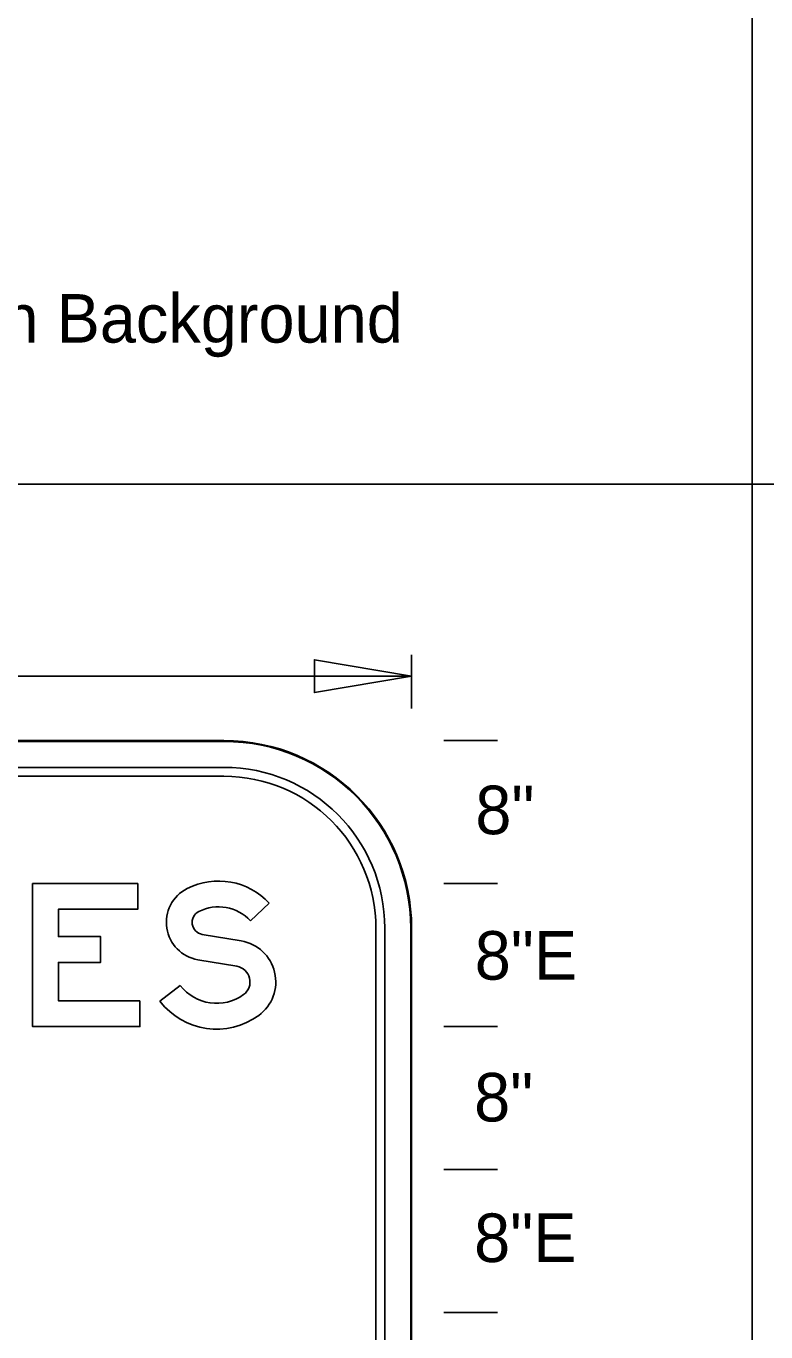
# Model space of a CAD drawing. Extents: x 0 to 770, y 0 to 495.
# Drawn here: x 140.1 to 193.5, y 103.8 to 198 of the extents above; entities that cross this region are included whole.
import ezdxf

# ---------------------------------------------------------------- set-up
doc = ezdxf.new("R2010")
doc.units = 0
for name, color, linetype in [('Dimension', 7, 'Continuous'), ('GSBWFill', 7, 'Continuous'), ('GSColorFill', 7, 'Continuous'), ('GSDims', 7, 'Continuous'), ('GSOutline', 7, 'Continuous'), ('SheetLines_dp', 7, 'Continuous'), ('TextStructures', 7, 'Continuous')]:
    doc.layers.add(name, color=color, linetype=linetype)

msp = doc.modelspace()

# ---------------------------------------------------------------- linework, layer by layer
at = {"layer": 'Dimension'}
msp.add_lwpolyline([(167.929, 151.141), (160.912, 152.33), (160.912, 149.952)], close=True, dxfattribs=at)
at = {"layer": 'GSBWFill'}
for p, q in [((154.39, 146.499), (34.478, 146.499)), ((154.39, 144.565), (34.478, 144.565)), ((34.478, 143.92), (154.39, 143.92)), ((156.304, 133.502), (157.665, 134.766)), ((165.35, 132.961), (165.35, 67.202)), ((165.994, 67.202), (165.994, 132.961)), ((167.928, 67.202), (167.928, 132.961)), ((155.636, 132.046), (152.826, 132.521)), ((152.516, 130.69), (155.327, 130.215)), ((151.245, 128.833), (149.774, 127.7))]:
    msp.add_line(p, q, dxfattribs=at)
msp.add_lwpolyline([(148.33, 127.726), (142.45, 127.726), (142.45, 130.5), (145.493, 130.5), (145.493, 132.357), (142.45, 132.357), (142.45, 134.327), (148.175, 134.327), (148.175, 136.184), (140.594, 136.184), (140.594, 125.869), (148.33, 125.869)], close=True, dxfattribs=at)
for centre, radius, start, end in [((154.39, 132.961), 13.538, 0, 90), ((154.39, 132.961), 11.604, 0, 90), ((154.39, 132.961), 10.96, 0, 90), ((152.972, 133.385), 2.733, 116.91229, 260.40871), ((153.999, 131.362), 5.003, 42.87588, 116.91229), ((152.972, 133.385), 0.877, 116.91229, 260.40871), ((153.999, 131.362), 3.146, 42.87588, 116.91229), ((155.138, 129.096), 2.991, 306.12299, 80.40871), ((155.138, 129.096), 1.135, 306.12299, 80.40871), ((153.861, 130.846), 3.301, 217.58951, 306.12299), ((153.861, 130.846), 5.158, 217.5895, 306.12298)]:
    msp.add_arc(centre, radius, start, end, dxfattribs=at)
at = {"layer": 'GSColorFill'}
for p, q in [((154.39, 146.499), (34.478, 146.499)), ((154.39, 146.499), (34.478, 146.499)), ((34.478, 146.435), (154.39, 146.435)), ((154.39, 144.565), (34.478, 144.565)), ((34.478, 143.92), (154.39, 143.92)), ((156.304, 133.502), (157.665, 134.766)), ((165.35, 132.961), (165.35, 67.202)), ((165.994, 67.202), (165.994, 132.961)), ((167.864, 132.961), (167.864, 67.202)), ((167.928, 67.202), (167.928, 132.961)), ((167.928, 67.202), (167.928, 132.961)), ((155.636, 132.046), (152.826, 132.521)), ((152.516, 130.69), (155.327, 130.215)), ((151.245, 128.833), (149.774, 127.7))]:
    msp.add_line(p, q, dxfattribs=at)
msp.add_lwpolyline([(148.33, 127.726), (142.45, 127.726), (142.45, 130.5), (145.493, 130.5), (145.493, 132.357), (142.45, 132.357), (142.45, 134.327), (148.175, 134.327), (148.175, 136.184), (140.594, 136.184), (140.594, 125.869), (148.33, 125.869)], close=True, dxfattribs=at)
for centre, radius, start, end in [((154.39, 132.961), 13.538, 0, 90), ((154.39, 132.961), 13.538, 0, 90), ((154.39, 132.961), 13.474, 0, 90), ((154.39, 132.961), 11.604, 0, 90), ((154.39, 132.961), 10.96, 0, 90), ((152.972, 133.385), 2.733, 116.91229, 260.40871), ((153.999, 131.362), 5.003, 42.87588, 116.91229), ((152.972, 133.385), 0.877, 116.91229, 260.40871), ((153.999, 131.362), 3.146, 42.87588, 116.91229), ((155.138, 129.096), 2.991, 306.12299, 80.40871), ((155.138, 129.096), 1.135, 306.12299, 80.40871), ((153.861, 130.846), 3.301, 217.58951, 306.12299), ((153.861, 130.846), 5.158, 217.5895, 306.12298)]:
    msp.add_arc(centre, radius, start, end, dxfattribs=at)
at = {"layer": 'GSDims'}
for p, q in [((167.929, 148.82), (167.929, 152.688)), ((20.939, 151.141), (167.929, 151.141)), ((170.249, 146.499), (174.118, 146.499)), ((170.249, 136.184), (174.118, 136.184)), ((170.249, 136.184), (174.118, 136.184)), ((170.249, 125.869), (174.118, 125.869)), ((170.249, 125.869), (174.118, 125.869)), ((170.249, 115.554), (174.118, 115.554)), ((170.249, 115.554), (174.118, 115.554)), ((170.249, 105.239), (174.118, 105.239)), ((170.249, 105.239), (174.118, 105.239))]:
    msp.add_line(p, q, dxfattribs=at)
at = {"layer": 'GSOutline'}
for p, q in [((154.39, 146.499), (34.478, 146.499)), ((154.39, 144.565), (34.478, 144.565)), ((154.39, 143.92), (34.478, 143.92)), ((156.304, 133.502), (157.665, 134.766)), ((165.35, 67.202), (165.35, 132.961)), ((165.994, 67.202), (165.994, 132.961)), ((167.928, 67.202), (167.928, 132.961)), ((155.636, 132.046), (152.826, 132.521)), ((152.516, 130.69), (155.327, 130.215)), ((151.245, 128.833), (149.774, 127.7))]:
    msp.add_line(p, q, dxfattribs=at)
msp.add_lwpolyline([(148.33, 127.726), (142.45, 127.726), (142.45, 130.5), (145.493, 130.5), (145.493, 132.357), (142.45, 132.357), (142.45, 134.327), (148.175, 134.327), (148.175, 136.184), (140.594, 136.184), (140.594, 125.869), (148.33, 125.869)], close=True, dxfattribs=at)
for centre, radius, start, end in [((154.39, 132.961), 13.538, 0, 90), ((154.39, 132.961), 11.604, 0, 90), ((154.39, 132.961), 10.96, 0, 90), ((152.972, 133.385), 2.733, 116.91229, 260.40871), ((153.999, 131.362), 5.003, 42.87588, 116.91229), ((152.972, 133.385), 0.877, 116.91229, 260.40871), ((153.999, 131.362), 3.146, 42.87588, 116.91229), ((155.138, 129.096), 2.991, 306.12299, 80.40871), ((155.138, 129.096), 1.135, 306.12299, 80.40871), ((153.861, 130.846), 3.301, 217.58951, 306.12299), ((153.861, 130.846), 5.158, 217.5895, 306.12298)]:
    msp.add_arc(centre, radius, start, end, dxfattribs=at)
at = {"layer": 'SheetLines_dp'}
for p, q in [((192.5, 0), (192.5, 495)), ((0, 165), (770, 165))]:
    msp.add_line(p, q, dxfattribs=at)

# ---------------------------------------------------------------- texts
at = {"layer": 'TextStructures'}
for s, p in [('Fluorescent Yellow-Green Background', (86.909, 175.199)), ('8"', (172.524, 139.745)), ('8"E', (172.48, 129.253)), ('8"', (172.435, 119.027)), ('8"E', (172.435, 108.889))]:
    msp.add_text(s, height=3.5, dxfattribs=at).set_placement(p)

doc.saveas('drawing.dxf')
